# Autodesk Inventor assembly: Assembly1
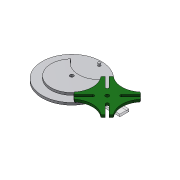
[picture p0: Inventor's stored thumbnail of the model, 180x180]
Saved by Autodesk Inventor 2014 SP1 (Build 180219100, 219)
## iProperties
Created: 2014-01
Part Number: Assembly1
Document SubType Name: Assembly
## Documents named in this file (4)
- E:\Documents\Homepage\inventorroom\sample\unit11\Assembly1.iam
- E:\Documents\Homepage\inventorroom\sample\unit11\Part8.ipt
- E:\Documents\Homepage\inventorroom\sample\unit11\Part6.ipt
- E:\Documents\Homepage\inventorroom\sample\unit11\Part7.ipt
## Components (3 placed, 3 different names)
1. Part8:1 — メイト:2, メイト:3, メイト:4, メイト:5
2. Part6:1 — メイト:2, メイト:4
3. Part7:1 — メイト:3, メイト:5
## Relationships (4: Mate 4)
- メイト:2 [Mate]: Part8:1 ↔ Part6:1
- メイト:3 [Mate]: Part8:1 ↔ Part7:1
- メイト:4 [Mate]: Part8:1 ↔ Part6:1
- メイト:5 [Mate]: Part8:1 ↔ Part7:1
